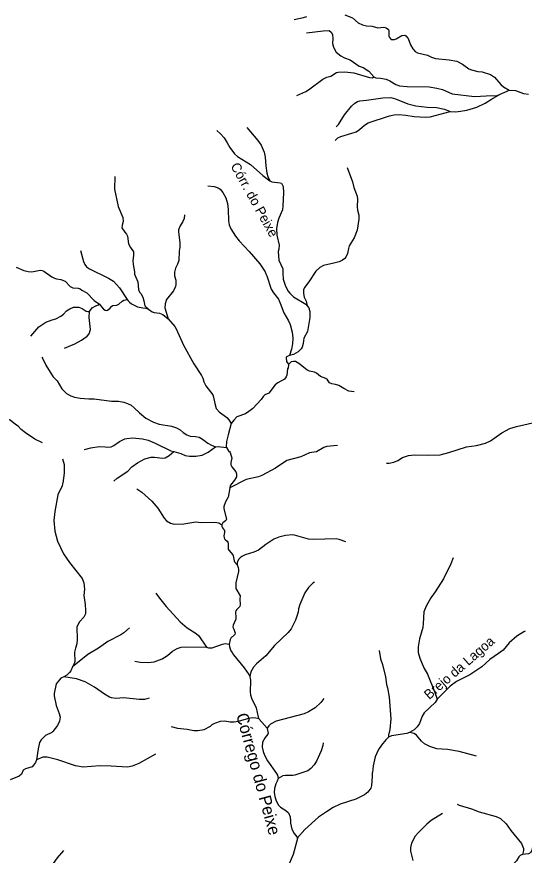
# Model space of a CAD drawing. Extents: x 280.4 to 335.6, y 8893.9 to 8949.5.
# Drawn here: x 321.05 to 329.44, y 8909.74 to 8923.61 of the extents above; entities that cross this region are included whole.
import ezdxf
from ezdxf.enums import TextEntityAlignment as Align

# ---------------------------------------------------------------- set-up
doc = ezdxf.new("R2010")
doc.units = 0
doc.header["$LTSCALE"] = 0.064
doc.layers.add('61', color=7, linetype='Continuous')
doc.layers.add('7', color=7, linetype='Continuous', lineweight=25)

msp = doc.modelspace()

# ---------------------------------------------------------------- linework, layer by layer
at = {"layer": '7'}
for points in [[(326.4729, 8923.6424), (326.6001, 8923.5899), (326.6962, 8923.5084), (326.7658, 8923.4734), (326.8333, 8923.4584), (326.9264, 8923.4523), (327.0231, 8923.4236), (327.1215, 8923.4363), (327.1567, 8923.4282), (327.1983, 8923.3971), (327.2046, 8923.3685), (327.2049, 8923.2876), (327.2164, 8923.2631), (327.2433, 8923.2352), (327.2981, 8923.232), (327.3255, 8923.2426), (327.4175, 8923.2997), (327.4667, 8923.3033), (327.4847, 8923.2918), (327.5206, 8923.2501), (327.5622, 8923.147), (327.5998, 8923.0782), (327.6385, 8923.036), (327.6756, 8923.0124), (327.8437, 8922.9759), (327.909, 8922.942), (327.9739, 8922.9179), (328.2011, 8922.8988), (328.3266, 8922.872), (328.4219, 8922.8231), (328.5256, 8922.7496), (328.5688, 8922.7321), (328.6721, 8922.7057), (328.7448, 8922.6971), (328.8839, 8922.6559), (328.951, 8922.6079), (329.0561, 8922.4886), (329.0993, 8922.4486), (329.1916, 8922.3936)], [(325.6366, 8923.5642), (325.7941, 8923.5949), (325.8491, 8923.6125)], [(325.8405, 8923.3421), (326.1179, 8923.3773), (326.2164, 8923.3819), (326.2491, 8923.3556), (326.269, 8923.3131), (326.2754, 8923.2517), (326.2739, 8923.1653), (326.2858, 8923.1054), (326.3321, 8923.0251), (326.4081, 8922.9605), (326.4675, 8922.9286), (326.5649, 8922.8973), (326.7138, 8922.7895), (326.7792, 8922.7709), (326.872, 8922.7103), (326.9564, 8922.6159)], [(325.6833, 8922.309), (325.8287, 8922.3742), (325.8757, 8922.4017), (326.1131, 8922.5778), (326.1758, 8922.6071), (326.2409, 8922.6258), (326.3347, 8922.6846), (326.3667, 8922.6943), (326.4754, 8922.6959), (326.6257, 8922.6815), (326.8845, 8922.6028), (326.9327, 8922.5986), (326.9564, 8922.6159)], [(326.9564, 8922.6159), (326.9853, 8922.5999), (327.0624, 8922.5949), (327.1567, 8922.5775), (327.2213, 8922.5484), (327.3173, 8922.491), (327.379, 8922.4677), (327.5078, 8922.4545), (327.8715, 8922.451), (327.9947, 8922.4304), (328.0878, 8922.4041), (328.2522, 8922.3325), (328.6172, 8922.2915), (328.9096, 8922.3072), (328.9807, 8922.3021), (329.0421, 8922.3272)], [(329.0421, 8922.3272), (329.1621, 8922.3761), (329.1916, 8922.3936)], [(329.1916, 8922.3936), (329.2997, 8922.3903), (329.4292, 8922.3406), (329.5141, 8922.3265)], [(326.3313, 8921.7878), (326.37, 8921.8296), (326.4705, 8921.9863), (326.5826, 8922.1297), (326.6407, 8922.1813), (326.6869, 8922.2075), (326.7224, 8922.2194), (326.8323, 8922.2288), (327.103, 8922.2674), (327.2366, 8922.2721), (327.3156, 8922.2511), (327.5144, 8922.1684), (327.6499, 8922.1373), (327.838, 8922.1122), (327.9908, 8922.1057), (328.1221, 8922.082), (328.2183, 8922.0415)], [(328.2183, 8922.0415), (328.3081, 8922.0387), (328.388, 8922.0455), (328.4949, 8922.0663), (328.6553, 8922.1112), (328.7975, 8922.1778), (328.9015, 8922.2465), (329.0421, 8922.3272)], [(326.3152, 8921.563), (326.3611, 8921.6061), (326.4063, 8921.6298), (326.5927, 8921.6822), (326.6609, 8921.7076), (326.7189, 8921.7439), (326.7978, 8921.8141), (326.8589, 8921.8541), (327.2136, 8921.968), (327.2896, 8921.984), (327.3678, 8921.9906), (327.4822, 8921.9811), (327.6197, 8921.9584), (327.8092, 8921.9459), (327.8882, 8921.9528), (328.2183, 8922.0415)], [(324.3594, 8921.7302), (324.4192, 8921.675), (324.4791, 8921.604), (324.5319, 8921.5241), (324.5714, 8921.4492), (324.6532, 8921.3429), (324.7009, 8921.2961), (324.9128, 8921.1627), (325.1216, 8920.9842), (325.2357, 8920.8979)], [(324.8538, 8921.7769), (325.0361, 8921.5619), (325.0903, 8921.4852), (325.1405, 8921.3686), (325.159, 8921.2853), (325.1672, 8921.1406), (325.1833, 8921.0247), (325.1991, 8920.9678), (325.2357, 8920.8979)], [(326.5116, 8921.1166), (326.6003, 8920.8801), (326.6228, 8920.7843), (326.6815, 8920.6415), (326.6866, 8920.5899), (326.6802, 8920.4667), (326.685, 8920.4115), (326.7074, 8920.3292), (326.709, 8920.2587), (326.6797, 8920.0798), (326.6318, 8919.9542), (326.5463, 8919.8179), (326.5333, 8919.778), (326.5201, 8919.691), (326.4929, 8919.6334), (326.4727, 8919.6099), (326.4363, 8919.585), (326.3794, 8919.5582), (326.2931, 8919.5326), (326.1231, 8919.495), (326.0629, 8919.4638), (325.9977, 8919.4004), (325.8806, 8919.2232), (325.8106, 8919.1318), (325.7939, 8919.0911), (325.7911, 8919.0345), (325.8034, 8918.9728), (325.8343, 8918.9064), (325.8545, 8918.8293)], [(322.6715, 8920.9655), (322.6644, 8920.758), (322.7268, 8920.4682), (322.8029, 8920.2906), (322.8097, 8920.2252), (322.7924, 8920.1642), (322.788, 8920.1206), (322.8376, 8920.0445), (322.8646, 8920.0148), (322.8831, 8919.9775), (322.9001, 8919.8557), (322.9295, 8919.7939), (322.9793, 8919.7195), (322.9826, 8919.6621), (322.9717, 8919.5791), (322.9737, 8919.5103), (322.9981, 8919.3899), (322.9992, 8919.3535), (323.0529, 8919.2271), (323.0631, 8919.1007), (323.077, 8919.0552), (323.1011, 8919.0296), (323.1347, 8918.9737), (323.1537, 8918.9104), (323.1684, 8918.8258), (323.2263, 8918.7723)], [(325.2357, 8920.8979), (325.2696, 8920.8802), (325.4077, 8920.8644), (325.4261, 8920.8565), (325.4551, 8920.8033), (325.4615, 8920.6984), (325.4513, 8920.4824), (325.442, 8920.4162), (325.3848, 8920.2762), (325.3644, 8920.2075), (325.3464, 8920.1011), (325.3507, 8919.9977), (325.3878, 8919.8292), (325.3848, 8919.7652), (325.3753, 8919.7285), (325.3849, 8919.5813), (325.4498, 8919.4389), (325.4488, 8919.3678), (325.4571, 8919.2671), (325.4897, 8919.1699), (325.5331, 8919.0775), (325.5629, 8919.0389), (325.6261, 8918.9782), (325.8314, 8918.8579), (325.8545, 8918.8293)], [(324.2103, 8920.8145), (324.317, 8920.8022), (324.3798, 8920.7787), (324.4122, 8920.7576), (324.4575, 8920.7026), (324.5059, 8920.6148), (324.5371, 8920.5193), (324.5467, 8920.4226), (324.5528, 8920.2343), (324.5646, 8920.1667), (324.5887, 8920.1029), (324.6657, 8919.9786), (324.7286, 8919.901), (324.8905, 8919.7292), (325.0691, 8919.5235), (325.1584, 8919.3917), (325.1671, 8919.359), (325.1866, 8919.3255), (325.2571, 8919.1017), (325.2941, 8919.043), (325.377, 8918.9385), (325.4073, 8918.8745), (325.467, 8918.7138), (325.5433, 8918.5803), (325.5702, 8918.517), (325.6017, 8918.392), (325.615, 8918.2924), (325.6118, 8918.198), (325.5915, 8918.1092), (325.5575, 8918.0084)], [(323.8257, 8920.3328), (323.8186, 8920.2696), (323.7981, 8920.2219), (323.7495, 8920.1534), (323.7248, 8920.0868), (323.7219, 8920.0502), (323.7455, 8919.8725), (323.747, 8919.7965), (323.7344, 8919.7317), (323.7275, 8919.5786), (323.7084, 8919.5143), (323.6766, 8919.4535), (323.6576, 8919.387), (323.6593, 8919.3238), (323.6798, 8919.251), (323.6799, 8919.1813), (323.6733, 8919.1496), (323.6401, 8919.0769), (323.528, 8918.9312), (323.5022, 8918.8632), (323.498, 8918.7971), (323.556, 8918.613)], [(322.1066, 8919.7443), (322.1519, 8919.5607), (322.1776, 8919.5113), (322.2055, 8919.4751), (322.2522, 8919.4389), (322.5695, 8919.2881), (322.6484, 8919.2383), (322.7491, 8919.1279), (322.8755, 8918.9328)], [(321.0378, 8919.4685), (321.1697, 8919.4108), (321.2359, 8919.3931), (321.297, 8919.3903), (321.4377, 8919.4173), (321.4728, 8919.4142), (321.498, 8919.4038), (321.6281, 8919.3097), (321.6729, 8919.2854), (321.7096, 8919.2736), (321.7807, 8919.2653), (321.8487, 8919.2375), (321.9356, 8919.145), (321.9554, 8919.1364), (321.9773, 8919.1278), (322.0653, 8919.1213), (322.0996, 8919.1101), (322.1281, 8919.0886), (322.206, 8919.0411), (322.3289, 8918.9162), (322.4191, 8918.8547)], [(322.4191, 8918.8547), (322.4487, 8918.8092), (322.4849, 8918.7722), (322.5111, 8918.7556), (322.534, 8918.7514), (322.5514, 8918.7543), (322.5885, 8918.7852), (322.6214, 8918.8239), (322.6394, 8918.8335), (322.697, 8918.8372), (322.7175, 8918.8444), (322.7375, 8918.8568), (322.7924, 8918.9071), (322.8233, 8918.9206), (322.8755, 8918.9328)], [(322.8755, 8918.9328), (322.8932, 8918.9095), (322.9134, 8918.8868), (322.9451, 8918.8607), (323.0483, 8918.8136), (323.1354, 8918.7939), (323.1843, 8918.7909), (323.2263, 8918.7723)], [(321.2841, 8918.3279), (321.4149, 8918.4797), (321.5281, 8918.5588), (321.6353, 8918.5984), (321.6943, 8918.6134), (321.7762, 8918.6542), (321.8247, 8918.6898), (321.8726, 8918.7452), (321.9297, 8918.7806), (321.9895, 8918.8036), (322.0742, 8918.8081), (322.1318, 8918.7857), (322.2002, 8918.7382), (322.2262, 8918.733), (322.2519, 8918.7355)], [(322.2519, 8918.7355), (322.2988, 8918.7957), (322.3567, 8918.8286), (322.4024, 8918.8428), (322.4191, 8918.8547)], [(323.2263, 8918.7723), (323.2882, 8918.7298), (323.32, 8918.7175), (323.408, 8918.7056), (323.4682, 8918.6834), (323.556, 8918.613)], [(325.8545, 8918.8293), (325.882, 8918.7952), (325.8967, 8918.7315), (325.8965, 8918.6347), (325.8567, 8918.4058), (325.7995, 8918.2915), (325.7877, 8918.2036), (325.7723, 8918.1441), (325.7546, 8918.116), (325.7039, 8918.0658), (325.6245, 8918.023), (325.5575, 8918.0084)], [(321.8395, 8918.1252), (322.0086, 8918.1995), (322.1184, 8918.2608), (322.2129, 8918.3279), (322.2448, 8918.3662), (322.2693, 8918.4345), (322.247, 8918.6322), (322.2519, 8918.7355)], [(323.556, 8918.613), (323.6659, 8918.4833), (323.6886, 8918.445), (323.8063, 8918.1749), (323.977, 8917.8684), (324.1037, 8917.6758), (324.1244, 8917.6325), (324.1409, 8917.5731), (324.1746, 8917.5046), (324.2904, 8917.3534), (324.3053, 8917.3169), (324.3227, 8917.2128), (324.3495, 8917.1276), (324.397, 8917.0772), (324.5227, 8916.9817), (324.5573, 8916.9439), (324.5981, 8916.8803)], [(321.4623, 8917.9761), (321.4826, 8917.9519), (321.5322, 8917.8454), (321.6017, 8917.7283), (321.654, 8917.6563), (321.7164, 8917.5856), (321.7944, 8917.4552), (321.8738, 8917.3797), (321.9416, 8917.3392), (322.0055, 8917.3181), (322.0994, 8917.2997), (322.2398, 8917.2889), (322.3285, 8917.2887), (322.6148, 8917.2521), (322.7339, 8917.2519), (322.8212, 8917.2349), (322.881, 8917.2148), (322.9392, 8917.1838), (322.9928, 8917.1427), (323.0776, 8917.0581), (323.1858, 8916.9706), (323.3091, 8916.9011), (323.4049, 8916.8683), (323.6079, 8916.839), (323.692, 8916.8125), (323.7502, 8916.7786), (323.8044, 8916.7312), (323.8623, 8916.6923), (323.9192, 8916.6734), (324.0077, 8916.6681), (324.0637, 8916.6539), (324.1213, 8916.6219), (324.2123, 8916.5539), (324.2678, 8916.5231), (324.339, 8916.4945)], [(325.5575, 8918.0084), (325.5128, 8917.9825), (325.5035, 8917.9659), (325.5081, 8917.9096), (325.5406, 8917.8665), (325.5426, 8917.8577)], [(325.5426, 8917.8577), (325.5457, 8917.8439), (325.5363, 8917.8005), (325.5266, 8917.7854), (325.5171, 8917.6816), (325.5068, 8917.6521), (325.476, 8917.6127), (325.3681, 8917.557), (325.3212, 8917.5211), (325.219, 8917.3837), (325.1545, 8917.3542), (325.1311, 8917.3357), (325.0899, 8917.2771), (324.9524, 8917.13), (324.8902, 8917.0787), (324.8345, 8917.0426), (324.6908, 8916.9897), (324.6379, 8916.9385), (324.5981, 8916.8803)], [(326.6307, 8917.4055), (326.5434, 8917.4185), (326.4569, 8917.4612), (326.3749, 8917.5116), (326.3198, 8917.5292), (326.2586, 8917.5383), (326.2201, 8917.5543), (326.1892, 8917.6049), (326.1624, 8917.6274), (326.0705, 8917.6592), (326.0052, 8917.7158), (325.9732, 8917.7334), (325.8927, 8917.748), (325.846, 8917.7667), (325.7171, 8917.8735), (325.6612, 8917.9056), (325.6285, 8917.9093), (325.585, 8917.8994), (325.5426, 8917.8577)], [(321.4735, 8916.5636), (321.3509, 8916.6239), (321.1943, 8916.725), (321.1233, 8916.7814), (321.0721, 8916.8404), (321.0284, 8916.8667), (320.9384, 8916.9388), (320.8707, 8916.9687), (320.7988, 8916.9801), (320.7333, 8916.9736), (320.6439, 8916.9445), (320.5947, 8916.9078), (320.5416, 8916.8331), (320.481, 8916.6326), (320.4629, 8916.6056), (320.3786, 8916.5472)], [(324.5981, 8916.8803), (324.5434, 8916.6964), (324.5166, 8916.5826), (324.5135, 8916.4971), (324.5198, 8916.4862)], [(327.1668, 8916.2235), (327.2062, 8916.2236), (327.2833, 8916.2425), (327.3492, 8916.272), (327.4292, 8916.3182), (327.5266, 8916.3537), (327.6248, 8916.3661), (327.8398, 8916.3582), (328.0539, 8916.3648), (328.1947, 8916.4008), (328.4849, 8916.4972), (328.6503, 8916.52), (328.8007, 8916.558), (328.883, 8916.5967), (329.0724, 8916.7251), (329.2012, 8916.7965), (329.313, 8916.8339), (329.6296, 8916.9012), (329.6982, 8916.9222)], [(322.1705, 8916.4513), (322.2751, 8916.4778), (322.4125, 8916.5005), (322.5117, 8916.4972), (322.5557, 8916.4895), (322.6106, 8916.496), (322.6569, 8916.5167), (322.7465, 8916.5854), (322.8367, 8916.6263), (322.8682, 8916.6347), (322.9627, 8916.6427), (323.1305, 8916.6271), (323.2232, 8916.6041), (323.3378, 8916.5586), (323.5975, 8916.4314), (323.6471, 8916.4176)], [(322.654, 8915.93), (322.7131, 8915.9794), (322.8866, 8916.091), (322.9533, 8916.1657), (323.0482, 8916.2317), (323.1666, 8916.2956), (323.2699, 8916.3227), (323.3287, 8916.3228), (323.4592, 8916.3101), (323.504, 8916.3167), (323.5678, 8916.3501), (323.6471, 8916.4176)], [(323.6471, 8916.4176), (323.7614, 8916.3857), (323.8335, 8916.3534), (323.9068, 8916.3417), (324.0101, 8916.3405), (324.1149, 8916.3581), (324.2166, 8916.4073), (324.339, 8916.4945)], [(324.339, 8916.4945), (324.3793, 8916.4998), (324.5198, 8916.4862)], [(324.5198, 8916.4862), (324.5583, 8916.4191), (324.569, 8916.4198), (324.5786, 8916.4043), (324.6039, 8916.3077), (324.5884, 8916.2358), (324.5887, 8916.2006), (324.6038, 8916.1647), (324.6699, 8916.0824), (324.6841, 8916.0477), (324.6842, 8915.998), (324.651, 8915.9429), (324.5871, 8915.8637), (324.5728, 8915.8212), (324.5719, 8915.8164)], [(326.3519, 8916.5167), (326.1754, 8916.5004), (326.1262, 8916.4824), (326.0059, 8916.4143), (325.8886, 8916.3959), (325.7477, 8916.3314), (325.5174, 8916.2674), (325.3313, 8916.145), (325.1006, 8916.0226), (325.0449, 8915.9997), (324.8442, 8915.955), (324.5719, 8915.8164)], [(321.8067, 8916.295), (321.8343, 8916.2039), (321.8343, 8916.0612), (321.8133, 8915.8943), (321.8044, 8915.8849), (321.7989, 8915.8494), (321.7314, 8915.7), (321.6777, 8915.4282), (321.6649, 8915.2794), (321.6779, 8915.0997), (321.7211, 8914.9372), (321.8244, 8914.7275), (321.9212, 8914.5806), (322.1305, 8914.3167), (322.1603, 8914.2477), (322.1702, 8914.1422), (322.1575, 8914.0367), (322.1805, 8913.8902), (322.1894, 8913.7879), (322.1842, 8913.7346), (322.157, 8913.6767), (322.0871, 8913.5993), (322.0425, 8913.5174), (322.0502, 8913.3098), (322.0437, 8913.2396), (322.0197, 8913.1684), (322.0075, 8913.1017), (322.0102, 8912.9481), (322.0016, 8912.9147), (321.9741, 8912.857)], [(323.038, 8915.8015), (323.1204, 8915.7466), (323.2847, 8915.5971), (323.3804, 8915.479), (323.4859, 8915.3174), (323.5273, 8915.2732), (323.5941, 8915.2313), (323.655, 8915.2162), (323.8117, 8915.2242), (324.0118, 8915.2545), (324.1007, 8915.245), (324.3253, 8915.2513), (324.3926, 8915.2371), (324.4435, 8915.2038)], [(324.5719, 8915.8164), (324.5434, 8915.664), (324.5004, 8915.5872), (324.4764, 8915.5097), (324.4766, 8915.4703), (324.5206, 8915.301), (324.5154, 8915.2852), (324.5022, 8915.2708), (324.4564, 8915.2383), (324.4435, 8915.2038)], [(324.4435, 8915.2038), (324.4435, 8915.1809), (324.4513, 8915.1572), (324.471, 8915.1329), (324.4829, 8915.1152), (324.4878, 8915.0801), (324.4797, 8915.049), (324.4746, 8915.0249), (324.4809, 8914.9899), (324.4902, 8914.9662), (324.5286, 8914.935), (324.5402, 8914.9201), (324.5466, 8914.8931), (324.5436, 8914.8256), (324.5478, 8914.8055), (324.5544, 8914.7873), (324.6228, 8914.7082), (324.6273, 8914.694), (324.6425, 8914.6124), (324.6516, 8914.5929), (324.6936, 8914.5463)], [(326.4893, 8914.9261), (326.382, 8914.9652), (326.3342, 8914.9746), (325.9597, 8914.9619), (325.8742, 8914.9715), (325.6438, 8915.037), (325.6122, 8915.0401), (325.4955, 8915.0297), (325.384, 8915.0032), (325.2998, 8914.9689), (325.1705, 8914.8819), (325.0482, 8914.7889), (324.9705, 8914.7561), (324.8251, 8914.7124), (324.77, 8914.682), (324.7441, 8914.6606), (324.7211, 8914.6372), (324.6992, 8914.5984), (324.6942, 8914.5759), (324.6936, 8914.5463)], [(328.2665, 8914.6579), (328.2284, 8914.5611), (328.1062, 8914.3105), (327.9703, 8914.0977), (327.8981, 8913.999), (327.8199, 8913.8616), (327.7839, 8913.7653), (327.7723, 8913.5746), (327.7627, 8913.5106), (327.7099, 8913.3187), (327.686, 8913.1908), (327.6877, 8913.0956), (327.7167, 8912.9989), (327.7833, 8912.8403), (327.8427, 8912.7373), (327.9595, 8912.4494), (328.0004, 8912.322)], [(324.6936, 8914.5463), (324.7126, 8914.4977), (324.7194, 8914.4672), (324.7159, 8914.436), (324.673, 8914.247), (324.6718, 8914.1509), (324.7418, 8914.032), (324.7387, 8913.9751), (324.7465, 8913.8857), (324.7381, 8913.8564), (324.6881, 8913.8044), (324.6717, 8913.7833), (324.6656, 8913.7623), (324.6745, 8913.6706), (324.6715, 8913.6433), (324.629, 8913.5481), (324.6221, 8913.5153), (324.6371, 8913.4814), (324.6521, 8913.4474), (324.6597, 8913.4151), (324.6542, 8913.3947), (324.5917, 8913.3306), (324.5773, 8913.3082), (324.5602, 8913.2307)], [(325.9723, 8914.2576), (325.9465, 8914.2413), (325.8742, 8914.1686), (325.8125, 8914.0792), (325.7319, 8913.8902), (325.7114, 8913.8166), (325.7033, 8913.759), (325.6618, 8913.628), (325.5859, 8913.486), (325.5378, 8913.4246), (325.311, 8913.2086), (325.1709, 8913.0402), (325.0132, 8912.9063), (324.9646, 8912.8545), (324.9184, 8912.774), (324.9028, 8912.6976)], [(323.3483, 8914.078), (323.4103, 8913.9909), (323.5232, 8913.854), (323.7508, 8913.602), (323.8696, 8913.5038), (324.0189, 8913.4106), (324.0604, 8913.3697), (324.1898, 8913.1822)], [(322.9135, 8913.5006), (322.8184, 8913.4175), (322.7721, 8913.3855), (322.5584, 8913.2771), (322.4025, 8913.1648), (322.2233, 8913.0594), (321.9741, 8912.857)], [(329.4556, 8913.4456), (329.4359, 8913.4379), (329.319, 8913.3642), (329.1938, 8913.2519), (329.0934, 8913.134), (329.0188, 8913.0768), (328.8706, 8912.9809), (328.7409, 8912.8554), (328.5442, 8912.7258), (328.3215, 8912.6125), (328.2165, 8912.5353), (328.0004, 8912.322)], [(324.1898, 8913.1822), (324.2223, 8913.1724), (324.2556, 8913.1691), (324.2836, 8913.1708), (324.4515, 8913.2347), (324.4982, 8913.244), (324.5302, 8913.2373), (324.5602, 8913.2307)], [(324.5602, 8913.2307), (324.5679, 8913.1899), (324.5917, 8913.1232), (324.6101, 8913.0925), (324.6315, 8913.0572), (324.8102, 8912.8429), (324.8885, 8912.7307), (324.9028, 8912.6976)], [(323.0013, 8912.9492), (323.0907, 8912.9357), (323.2218, 8912.9277), (323.321, 8912.9387), (323.4566, 8912.9904), (323.5433, 8913.0451), (323.6234, 8913.1158), (323.7024, 8913.1595), (323.7663, 8913.1803), (323.8409, 8913.1868), (324.1862, 8913.1826), (324.1898, 8913.1822)], [(327.0437, 8913.129), (327.0674, 8912.9894), (327.0984, 8912.8963), (327.1501, 8912.6909), (327.1665, 8912.5679), (327.1822, 8912.5102), (327.2078, 8912.3553), (327.2335, 8911.9986), (327.2206, 8911.8225), (327.1984, 8911.727), (327.1988, 8911.6956)], [(321.9741, 8912.857), (321.943, 8912.7917), (321.9215, 8912.7614), (321.8764, 8912.7202), (321.8278, 8912.6941)], [(321.8278, 8912.6941), (321.7812, 8912.6691), (321.7542, 8912.6441), (321.7037, 8912.5779), (321.6684, 8912.4172), (321.6684, 8912.3761), (321.7028, 8912.2175), (321.7534, 8912.0852), (321.7655, 8912.024), (321.7554, 8911.9584), (321.7236, 8911.8891), (321.6485, 8911.7887), (321.6314, 8911.7738), (321.5259, 8911.7216), (321.4556, 8911.6506), (321.426, 8911.6066), (321.4028, 8911.5012), (321.3771, 8911.3207)], [(323.2381, 8912.3371), (323.1596, 8912.3197), (323.0739, 8912.3167), (322.821, 8912.3454), (322.69, 8912.3328), (322.6188, 8912.3422), (322.5822, 8912.3556), (322.5, 8912.4054), (322.334, 8912.521), (322.1814, 8912.6102), (322.039, 8912.6605), (321.8278, 8912.6941)], [(324.9028, 8912.6976), (324.9084, 8912.667), (324.9143, 8912.6348), (324.9082, 8912.4359), (324.9142, 8912.3932), (324.929, 8912.3408), (325.0104, 8912.1807), (325.0402, 8912.0243), (325.0529, 8912.0047)], [(326.1266, 8912.3311), (326.0772, 8912.2688), (325.9822, 8912.1766), (325.8756, 8912.1121), (325.8052, 8912.0794), (325.3403, 8911.9573), (325.2467, 8911.9084), (325.2201, 8911.8833), (325.1902, 8911.841)], [(328.0004, 8912.322), (327.9685, 8912.2667), (327.789, 8912.0979), (327.7556, 8912.0416), (327.7101, 8911.9224), (327.6727, 8911.8668), (327.6218, 8911.8173), (327.5462, 8911.7714)], [(323.6008, 8911.8678), (323.7087, 8911.8434), (323.8654, 8911.8273), (323.978, 8911.805), (324.0445, 8911.8018), (324.1512, 8911.8221), (324.2524, 8911.8734), (324.2836, 8911.9026), (324.3239, 8911.9262), (324.4169, 8911.9587), (324.4923, 8911.9664), (324.5812, 8911.9502), (324.6441, 8911.9473), (324.716, 8911.9607), (324.8898, 8912.0106), (324.9483, 8912.019), (325.0059, 8912.0161), (325.0529, 8912.0047)], [(325.0529, 8912.0047), (325.0601, 8911.9936), (325.1902, 8911.841)], [(325.1902, 8911.841), (325.1934, 8911.8373), (325.2052, 8911.7625), (325.1992, 8911.7449), (325.1585, 8911.6892), (325.1133, 8911.6115), (325.1095, 8911.5278), (325.1229, 8911.4595), (325.1452, 8911.3965), (325.1967, 8911.3026), (325.3467, 8911.0938), (325.3613, 8911.0638), (325.369, 8911.0381), (325.3707, 8911.0123)], [(327.1988, 8911.6956), (327.1532, 8911.6519), (327.082, 8911.5624), (327.0342, 8911.4884), (326.975, 8911.3667), (326.9426, 8911.2219), (326.9329, 8911.1124), (326.9267, 8911.1052), (326.9296, 8911.0453), (326.9182, 8910.8975), (326.9035, 8910.8513), (326.854, 8910.786), (326.8006, 8910.7403), (326.6577, 8910.6694), (326.3986, 8910.5847), (326.2835, 8910.5303), (326.1715, 8910.4615), (326.0399, 8910.3683), (325.8133, 8910.1673), (325.6886, 8910.0258)], [(327.5462, 8911.7714), (327.4995, 8911.7573), (327.2487, 8911.7167), (327.1988, 8911.6956)], [(328.65, 8911.3808), (328.3643, 8911.4598), (328.173, 8911.4915), (328.085, 8911.4931), (327.9972, 8911.5029), (327.8834, 8911.5376), (327.7941, 8911.583), (327.7448, 8911.6294), (327.6629, 8911.727), (327.623, 8911.7522), (327.5462, 8911.7714)], [(326.1169, 8911.6026), (326.1109, 8911.5553), (326.0818, 8911.4701), (326.0082, 8911.2997), (325.97, 8911.2373), (325.9155, 8911.1756), (325.8623, 8911.1396), (325.6496, 8911.0645), (325.6145, 8911.0582), (325.4941, 8911.0613), (325.4515, 8911.0531), (325.3707, 8911.0123)], [(321.3771, 8911.3207), (321.3583, 8911.2733), (321.3294, 8911.2283), (321.3026, 8911.2019), (321.1954, 8911.1685), (321.1584, 8911.1458), (321.1278, 8911.0843), (321.0889, 8911.0487), (320.9394, 8910.9881)], [(323.3451, 8911.4134), (323.0704, 8911.2571), (322.9604, 8911.2143), (322.8796, 8911.1989), (322.6084, 8911.2164), (322.4249, 8911.2181), (322.148, 8911.1991), (322.0215, 8911.2197), (321.7288, 8911.3219), (321.5537, 8911.3634), (321.4818, 8911.3617), (321.3771, 8911.3207)], [(325.3707, 8911.0123), (325.3544, 8910.9677), (325.345, 8910.9446), (325.3345, 8910.9216), (325.3112, 8910.8438), (325.3049, 8910.7791), (325.3164, 8910.711), (325.3397, 8910.643), (325.3789, 8910.5714), (325.4097, 8910.5376), (325.4991, 8910.4827), (325.5421, 8910.4408), (325.5699, 8910.374), (325.5688, 8910.3457), (325.5751, 8910.3368), (325.5792, 8910.27), (325.5976, 8910.1722), (325.6365, 8910.1032), (325.6841, 8910.048), (325.6886, 8910.0258)], [(328.3344, 8910.5875), (328.3638, 8910.5708), (328.5674, 8910.5111), (328.6945, 8910.457), (328.9766, 8910.3832), (329.047, 8910.348), (329.1446, 8910.26), (329.2208, 8910.1515), (329.3955, 8909.9354), (329.4276, 8909.8537), (329.4275, 8909.8202), (329.4108, 8909.7542)], [(328.0913, 8910.4305), (327.9007, 8910.314), (327.8296, 8910.258), (327.6852, 8910.1121), (327.6369, 8910.0543), (327.5774, 8909.9418), (327.5598, 8909.8708), (327.5613, 8909.8081), (327.5978, 8909.6523)], [(325.6886, 8910.0258), (325.6906, 8910.0157), (325.623, 8909.7531), (325.5192, 8909.5228), (325.4982, 8909.4077), (325.479, 8909.3501), (325.4308, 8909.2615), (325.4059, 8909.2345), (325.3501, 8909.1984), (325.3291, 8909.1772), (325.3294, 8909.1518), (325.3605, 8909.1249), (325.3924, 8909.1084), (325.4093, 8909.0931), (325.4101, 8909.0711), (325.3994, 8909.0462), (325.3707, 8909.0181), (325.2946, 8908.9593), (325.2526, 8908.9187), (325.2118, 8908.8645)], [(329.7171, 8910.0174), (329.6617, 8909.9986), (329.626, 8909.9722), (329.6017, 8909.9483), (329.5852, 8909.9247), (329.5793, 8909.9116), (329.578, 8909.9007), (329.5745, 8909.8365), (329.5512, 8909.7892), (329.5101, 8909.7643), (329.4108, 8909.7542)], [(321.8219, 8909.8184), (321.7176, 8909.7002), (321.5856, 8909.5113), (321.4877, 8909.3291), (321.3251, 8909.0992), (321.3092, 8909.0653), (321.2855, 8908.9827), (321.2779, 8908.9278), (321.2778, 8908.7808), (321.2699, 8908.7207), (321.241, 8908.6561), (321.1893, 8908.5767)], [(329.4108, 8909.7542), (329.3742, 8909.7378), (329.3533, 8909.7157), (329.3136, 8909.647), (329.2714, 8909.6033), (329.1788, 8909.5694), (329.1071, 8909.5546), (329.0454, 8909.5315), (328.9726, 8909.458), (328.7972, 8909.4141)]]:
    msp.add_lwpolyline(points, dxfattribs=at)

# ---------------------------------------------------------------- texts
at = {"layer": '61'}
for s, height, rotation, p in [('Córr. do Peixe', 0.16, 299.055, (324.912, 8920.5441)), ('Brejo da Lagoa', 0.16, 40.914, (328.4179, 8912.7823)), ('Córrego do Peixe', 0.2, 285.369, (324.9506, 8911.059))]:
    msp.add_text(s, height=height, rotation=rotation, dxfattribs=at).set_placement(p, align=Align.CENTER)

doc.saveas('drawing.dxf')
